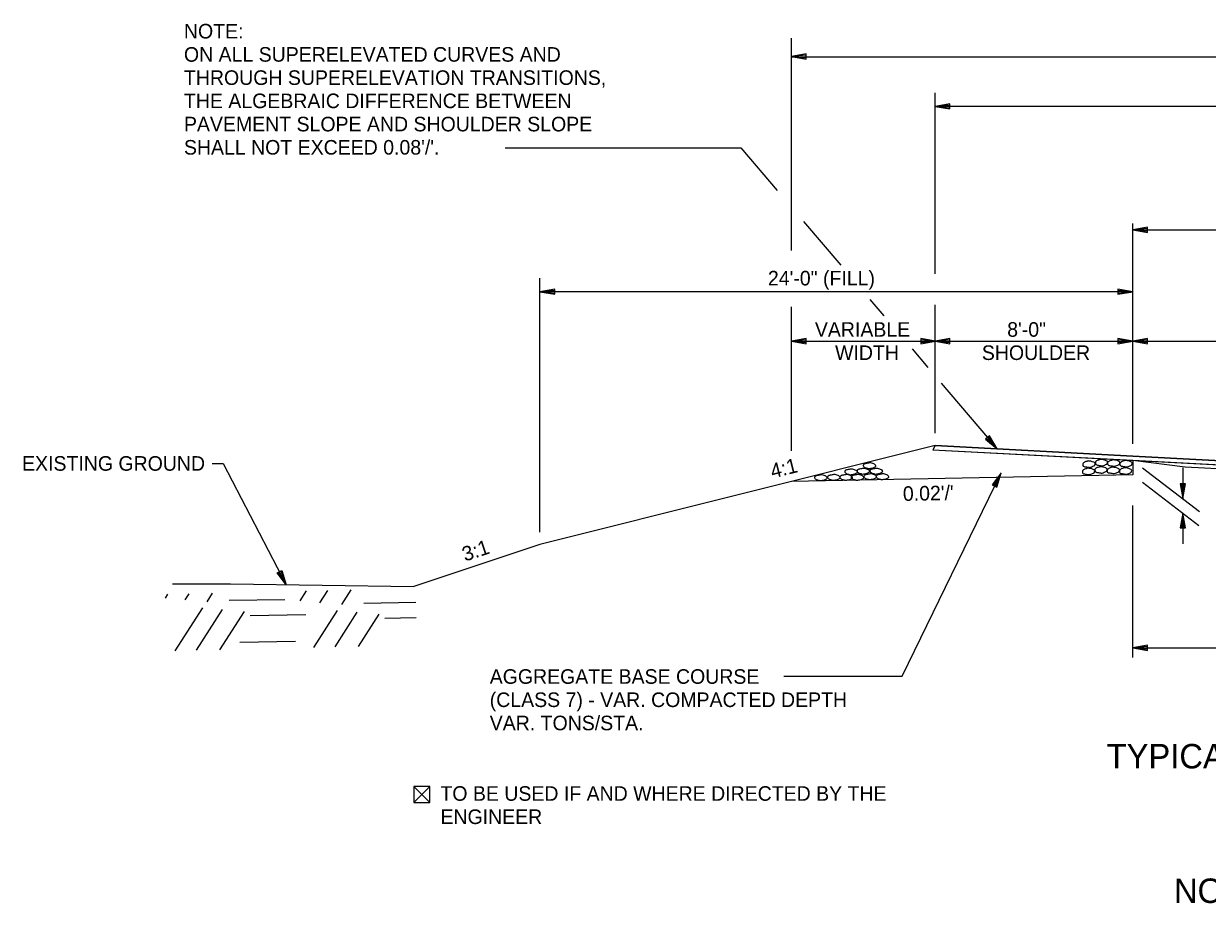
# Model space of a CAD drawing. Extents: x 1398183 to 1398373, y 1967240 to 1968889.
# Drawn here: x 1398192.77 to 1398240.69, y 1968386.9 to 1968422.5 of the extents above; entities that cross this region are included whole.
import ezdxf

# ---------------------------------------------------------------- set-up
doc = ezdxf.new("R2010")
doc.units = 0
for name, color, linetype in [('1', 7, 'Continuous'), ('10', 7, 'Continuous'), ('19', 7, 'Continuous'), ('42', 7, 'Continuous'), ('9', 7, 'Continuous'), ('Level 1', 7, 'Continuous')]:
    doc.layers.add(name, color=color, linetype=linetype)

# ---------------------------------------------------------------- blocks, each defined once
blk = doc.blocks.new('ROCKS')
at = {"layer": '1'}
blk.add_spline([(0.013, 0.06), (0.053, 0.053), (0.107, 0.033), (0.133, 0.013), (0.133, -0.007), (0.12, -0.033), (0.107, -0.04), (0.073, -0.053), (0.033, -0.067), (0.013, -0.067), (-0.02, -0.06), (-0.06, -0.053), (-0.087, -0.047), (-0.113, -0.02), (-0.113, -0.007), (-0.107, 0.02), (-0.087, 0.033), (-0.067, 0.047), (-0.033, 0.053), (-0.02, 0.06), (0.013, 0.06)], degree=3, dxfattribs=at)
blk = doc.blocks.new('4TO1 ABC')
at = {"layer": '1', "xscale": 0.1312491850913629, "yscale": 0.1312491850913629, "rotation": 180}
for p in [(0.00175, -0.00875), (-0.03325, -0.0385), (-0.016625, -0.023625), (0, -0.0385), (0.018375, -0.023625), (0.034125, -0.04025), (0.051625, -0.025375), (0.06475, -0.04025), (0.098, -0.04025), (0.133, -0.041125)]:
    blk.add_blockref('ROCKS', p, dxfattribs=at)

msp = doc.modelspace()

# ---------------------------------------------------------------- linework, layer by layer
at = {"layer": '10'}
for p, q in [((1398208.573, 1968391.62), (1398209.214, 1968390.979)), ((1398209.214, 1968391.62), (1398208.573, 1968390.979)), ((1398208.954, 1968390.979), (1398208.965, 1968390.979))]:
    msp.add_line(p, q, dxfattribs=at)
msp.add_lwpolyline([(1398208.965, 1968390.979), (1398209.214, 1968390.979), (1398209.214, 1968391.62), (1398208.573, 1968391.62), (1398208.573, 1968390.979), (1398208.954, 1968390.979)], dxfattribs=at)
at = {"layer": '19'}
for p, q in [((1398223.852, 1968413.316), (1398223.852, 1968421.911)), ((1398224.452, 1968421.273), (1398223.852, 1968421.168)), ((1398223.852, 1968421.168), (1398224.452, 1968421.063)), ((1398223.852, 1968421.15), (1398285.763, 1968421.15)), ((1398224.452, 1968421.218), (1398224.012, 1968421.183)), ((1398224.012, 1968421.153), (1398224.452, 1968421.113)), ((1398224.452, 1968421.063), (1398224.452, 1968421.273)), ((1398229.672, 1968412.378), (1398229.672, 1968419.698)), ((1398230.272, 1968419.255), (1398229.672, 1968419.15)), ((1398279.672, 1968419.15), (1398229.672, 1968419.15)), ((1398229.672, 1968419.15), (1398230.272, 1968419.045)), ((1398230.272, 1968419.2), (1398229.832, 1968419.165)), ((1398229.832, 1968419.135), (1398230.272, 1968419.095)), ((1398230.272, 1968419.045), (1398230.272, 1968419.255)), ((1398237.672, 1968405.498), (1398237.672, 1968414.415)), ((1398238.272, 1968414.255), (1398237.672, 1968414.15)), ((1398238.272, 1968414.2), (1398237.832, 1968414.165)), ((1398238.272, 1968414.045), (1398238.272, 1968414.255)), ((1398237.672, 1968414.15), (1398290.974, 1968414.15)), ((1398237.672, 1968414.15), (1398238.272, 1968414.045)), ((1398237.832, 1968414.135), (1398238.272, 1968414.095)), ((1398213.673, 1968401.922), (1398213.672, 1968412.197)), ((1398214.272, 1968411.755), (1398213.672, 1968411.65)), ((1398237.672, 1968411.65), (1398213.672, 1968411.65)), ((1398213.672, 1968411.65), (1398214.272, 1968411.545)), ((1398214.272, 1968411.7), (1398213.832, 1968411.665)), ((1398213.832, 1968411.635), (1398214.272, 1968411.595)), ((1398214.272, 1968411.545), (1398214.272, 1968411.755)), ((1398237.072, 1968411.755), (1398237.072, 1968411.545)), ((1398237.672, 1968411.65), (1398237.072, 1968411.755)), ((1398237.512, 1968411.665), (1398237.072, 1968411.7)), ((1398237.072, 1968411.545), (1398237.672, 1968411.65)), ((1398237.072, 1968411.595), (1398237.512, 1968411.635)), ((1398223.852, 1968405.209), (1398223.852, 1968411.032)), ((1398229.672, 1968405.922), (1398229.672, 1968411.112)), ((1398224.452, 1968409.755), (1398223.852, 1968409.65)), ((1398223.852, 1968409.65), (1398224.452, 1968409.545)), ((1398223.852, 1968409.65), (1398229.688, 1968409.65)), ((1398224.452, 1968409.7), (1398224.012, 1968409.665)), ((1398224.012, 1968409.635), (1398224.452, 1968409.595)), ((1398224.452, 1968409.545), (1398224.452, 1968409.755)), ((1398229.088, 1968409.755), (1398229.088, 1968409.545)), ((1398229.688, 1968409.65), (1398229.088, 1968409.755)), ((1398229.528, 1968409.665), (1398229.088, 1968409.7)), ((1398229.088, 1968409.545), (1398229.688, 1968409.65)), ((1398229.088, 1968409.595), (1398229.528, 1968409.635)), ((1398229.672, 1968409.65), (1398237.672, 1968409.65)), ((1398230.273, 1968409.755), (1398229.673, 1968409.65)), ((1398229.673, 1968409.65), (1398230.273, 1968409.545)), ((1398230.273, 1968409.7), (1398229.833, 1968409.665)), ((1398229.833, 1968409.635), (1398230.273, 1968409.595)), ((1398230.273, 1968409.545), (1398230.273, 1968409.755)), ((1398237.072, 1968409.755), (1398237.072, 1968409.545)), ((1398237.672, 1968409.65), (1398237.072, 1968409.755)), ((1398237.512, 1968409.665), (1398237.072, 1968409.7)), ((1398237.072, 1968409.545), (1398237.672, 1968409.65)), ((1398237.072, 1968409.595), (1398237.512, 1968409.635)), ((1398238.272, 1968409.755), (1398237.672, 1968409.65)), ((1398237.672, 1968409.65), (1398249.672, 1968409.65)), ((1398237.672, 1968409.65), (1398238.272, 1968409.545)), ((1398238.272, 1968409.7), (1398237.832, 1968409.665)), ((1398237.832, 1968409.635), (1398238.272, 1968409.595)), ((1398238.272, 1968409.545), (1398238.272, 1968409.755)), ((1398231.879, 1968405.817), (1398231.719, 1968405.682)), ((1398231.719, 1968405.682), (1398232.184, 1968405.289)), ((1398231.756, 1968405.709), (1398232.069, 1968405.403)), ((1398232.09, 1968405.418), (1398231.841, 1968405.778)), ((1398232.184, 1968405.289), (1398231.879, 1968405.817)), ((1398229.672, 1968405.422), (1398213.672, 1968401.422)), ((1398229.672, 1968405.422), (1398229.587, 1968405.252)), ((1398237.672, 1968404.827), (1398237.672, 1968404.244)), ((1398237.672, 1968404.244), (1398223.852, 1968403.967)), ((1398228.344, 1968396.084), (1398232.351, 1968404.315)), ((1398232.351, 1968404.315), (1398231.987, 1968403.826)), ((1398232.268, 1968404.178), (1398232.036, 1968403.805)), ((1398232.13, 1968403.756), (1398232.293, 1968404.165)), ((1398232.174, 1968403.734), (1398232.351, 1968404.315)), ((1398238.069, 1968404.523), (1398240.375, 1968402.758)), ((1398239.701, 1968404.524), (1398239.701, 1968403.274)), ((1398231.987, 1968403.826), (1398232.174, 1968403.734)), ((1398238.069, 1968403.94), (1398240.354, 1968402.191)), ((1398239.806, 1968403.874), (1398239.596, 1968403.874)), ((1398239.596, 1968403.874), (1398239.701, 1968403.274)), ((1398239.651, 1968403.874), (1398239.686, 1968403.434)), ((1398239.701, 1968403.274), (1398239.806, 1968403.874)), ((1398239.716, 1968403.434), (1398239.756, 1968403.874)), ((1398237.672, 1968396.849), (1398237.672, 1968402.998)), ((1398239.701, 1968402.691), (1398239.596, 1968402.091)), ((1398239.806, 1968402.091), (1398239.701, 1968402.691)), ((1398239.701, 1968402.691), (1398239.701, 1968401.441)), ((1398239.686, 1968402.531), (1398239.651, 1968402.091)), ((1398239.756, 1968402.091), (1398239.716, 1968402.531)), ((1398239.596, 1968402.091), (1398239.806, 1968402.091)), ((1398213.672, 1968401.422), (1398208.572, 1968399.722)), ((1398203.034, 1968400.276), (1398203.22, 1968400.372)), ((1398203.321, 1968399.928), (1398203.084, 1968400.297)), ((1398203.18, 1968400.348), (1398203.343, 1968399.942)), ((1398203.22, 1968400.372), (1398203.404, 1968399.792)), ((1398203.404, 1968399.792), (1398203.034, 1968400.276)), ((1398238.272, 1968397.344), (1398237.672, 1968397.239)), ((1398237.672, 1968397.239), (1398238.272, 1968397.134)), ((1398237.672, 1968397.239), (1398261.672, 1968397.239)), ((1398238.272, 1968397.289), (1398237.832, 1968397.254)), ((1398237.832, 1968397.224), (1398238.272, 1968397.184)), ((1398238.272, 1968397.134), (1398238.272, 1968397.344)), ((1398223.546, 1968396.084), (1398228.344, 1968396.084))]:
    msp.add_line(p, q, dxfattribs=at)
for points in [[(1398212.267, 1968417.472), (1398221.802, 1968417.472), (1398223.278, 1968415.74)], [(1398224.339, 1968414.495), (1398225.85, 1968412.722)], [(1398227.028, 1968411.339), (1398227.592, 1968410.678)], [(1398228.739, 1968409.331), (1398229.38, 1968408.579)], [(1398229.915, 1968407.952), (1398232.184, 1968405.29)], [(1398229.587, 1968405.252), (1398249.673, 1968404.196), (1398273.757, 1968402.92), (1398279.757, 1968402.602)], [(1398229.672, 1968405.422), (1398237.672, 1968404.998), (1398249.673, 1968404.362), (1398261.672, 1968403.726), (1398273.672, 1968403.09), (1398279.672, 1968402.772)], [(1398200.404, 1968404.698), (1398200.85, 1968404.698), (1398203.404, 1968399.792)]]:
    msp.add_lwpolyline(points, dxfattribs=at)
msp.add_lwpolyline([(1398229.587, 1968405.252), (1398237.672, 1968404.827), (1398249.673, 1968404.196), (1398273.757, 1968402.92), (1398279.757, 1968402.602), (1398279.672, 1968402.772), (1398273.672, 1968403.09), (1398249.673, 1968404.362), (1398237.672, 1968404.998), (1398229.672, 1968405.422)], close=True, dxfattribs=at)
at = {"layer": '42'}
for points in [[(1398237.672, 1968404.827), (1398239.799, 1968404.565), (1398249.675, 1968404.053), (1398258.847, 1968403.576), (1398261.672, 1968403.56)], [(1398198.802, 1968399.823), (1398201.14, 1968399.823), (1398208.572, 1968399.722)]]:
    msp.add_lwpolyline(points, dxfattribs=at)
at = {"layer": '9'}
for p, q in [((1398198.51, 1968399.248), (1398198.61, 1968399.405)), ((1398199.309, 1968399.175), (1398199.47, 1968399.425)), ((1398200.201, 1968399.103), (1398200.422, 1968399.448)), ((1398203.965, 1968399.137), (1398204.222, 1968399.538)), ((1398204.764, 1968399.063), (1398205.082, 1968399.559)), ((1398205.656, 1968398.992), (1398206.034, 1968399.581)), ((1398198.906, 1968397.117), (1398200.021, 1968398.858)), ((1398201.09, 1968399.161), (1398203.351, 1968399.197)), ((1398206.545, 1968399.05), (1398208.65, 1968399.083)), ((1398199.766, 1968397.137), (1398200.821, 1968398.784)), ((1398200.718, 1968397.16), (1398201.713, 1968398.712)), ((1398201.939, 1968398.551), (1398204.201, 1968398.586)), ((1398204.518, 1968397.25), (1398205.476, 1968398.746)), ((1398205.378, 1968397.271), (1398206.276, 1968398.673)), ((1398206.33, 1968397.294), (1398207.168, 1968398.601)), ((1398207.394, 1968398.44), (1398208.665, 1968398.459)), ((1398201.52, 1968397.465), (1398203.781, 1968397.5))]:
    msp.add_line(p, q, dxfattribs=at)

# ---------------------------------------------------------------- block references
at = {"layer": '19', "xscale": 14.999970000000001, "yscale": -14.999970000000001, "rotation": 180}
msp.add_blockref('4TO1 ABC', (1398227.023, 1968404.732), dxfattribs=at)
at = {"layer": 'Level 1', "xscale": 2.011654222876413, "yscale": 2.011654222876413, "rotation": 1.8263814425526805}
for p in [(1398235.88, 1968404.674), (1398236.388, 1968404.737), (1398236.882, 1968404.718), (1398237.379, 1968404.693), (1398235.863, 1968404.379), (1398236.371, 1968404.441), (1398236.865, 1968404.423), (1398237.362, 1968404.398)]:
    msp.add_blockref('ROCKS', p, dxfattribs=at)

# ---------------------------------------------------------------- texts
at = {"layer": '10'}
for s, height, p in [('24\'-0" (FILL)', 0.59001, (1398222.904, 1968411.902)), ('VARIABLE', 0.59, (1398224.805, 1968409.825)), ('8\'-0"', 0.59, (1398232.592, 1968409.825)), ('WIDTH', 0.59, (1398225.623, 1968408.885)), ('SHOULDER', 0.59, (1398231.566, 1968408.885)), ('EXISTING GROUND', 0.59001, (1398192.706, 1968404.403))]:
    msp.add_text(s, height=height, dxfattribs=at).set_placement(p)
for s, height, rotation, p in [('4:1', 0.59, 14.0362, (1398223.088, 1968404.088)), ('3:1', 0.59, 18.4349, (1398210.641, 1968400.723)), ('TO BE USED IF AND WHERE DIRECTED BY THE ', 0.59001, 360, (1398209.645, 1968391.046)), ('ENGINEER', 0.59, 360, (1398209.645, 1968390.106))]:
    msp.add_text(s, height=height, rotation=rotation, dxfattribs=at).set_placement(p)
at = {"layer": '19'}
for s, height, p in [('NOTE:', 0.59, (1398199.26, 1968421.897)), ('ON ALL SUPERELEVATED CURVES AND', 0.59001, (1398199.26, 1968420.957)), ('THROUGH SUPERELEVATION TRANSITIONS,', 0.59001, (1398199.26, 1968420.017)), ('THE ALGEBRAIC DIFFERENCE BETWEEN', 0.59001, (1398199.26, 1968419.077)), ('PAVEMENT SLOPE AND SHOULDER SLOPE', 0.59001, (1398199.26, 1968418.137)), ("SHALL NOT EXCEED 0.08'/'.", 0.59001, (1398199.26, 1968417.197)), ('TYPICAL SECTION OF IMPROVEMENT', 0.98999, (1398236.619, 1968392.356)), ('NORTHBOUND PASSING LANE', 0.98999, (1398239.344, 1968386.911))]:
    msp.add_text(s, height=height, dxfattribs=at).set_placement(p)
for s, height, rotation, p in [("0.02'/'", 0.59, 1.1458, (1398228.374, 1968403.18)), ('AGGREGATE BASE COURSE', 0.59001, 360, (1398211.641, 1968395.78)), ('(CLASS 7) - VAR. COMPACTED DEPTH', 0.59001, 360, (1398211.641, 1968394.84)), ('VAR. TONS/STA.', 0.59001, 360, (1398211.641, 1968393.9))]:
    msp.add_text(s, height=height, rotation=rotation, dxfattribs=at).set_placement(p)

doc.saveas('drawing.dxf')
